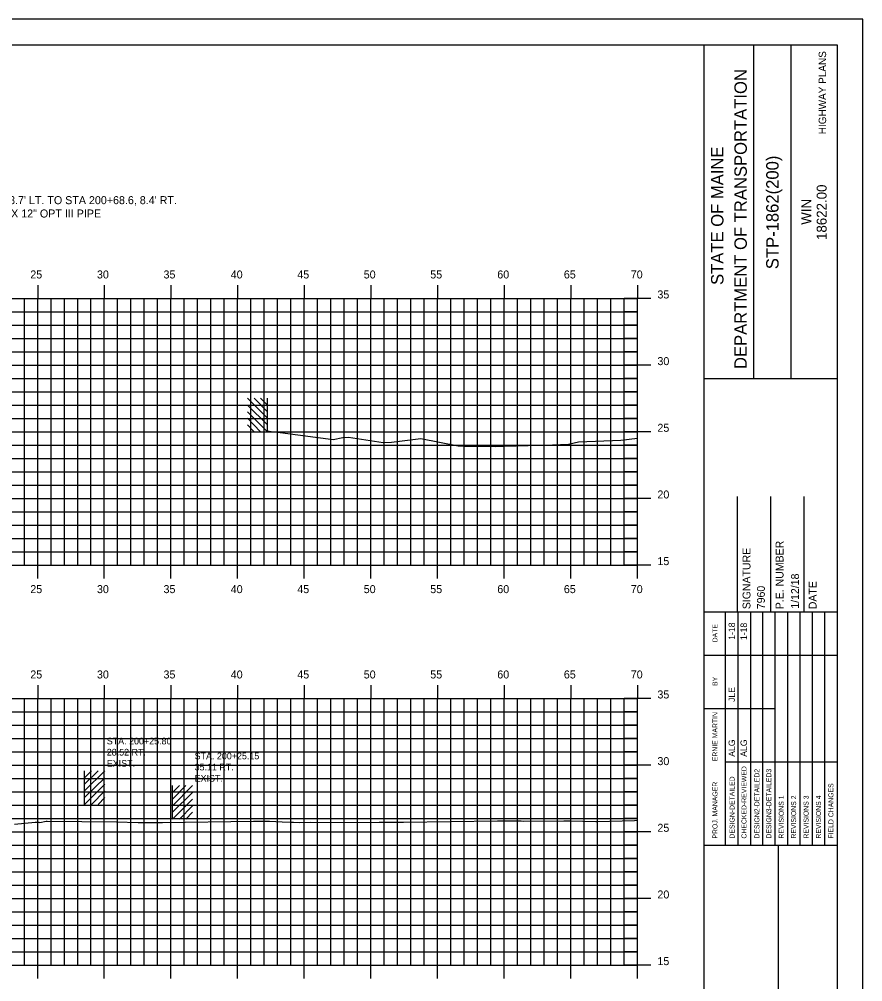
# Model space of a CAD drawing. Extents: x 1023237 to 1023407, y 394697 to 394807.
# Drawn here: x 1023343.3 to 1023406.6, y 394734.4 to 394806.5 of the extents above; entities that cross this region are included whole.
import ezdxf

# ---------------------------------------------------------------- set-up
doc = ezdxf.new("R2010")
doc.units = 0
for name, color, linetype in [('BORDER', 7, 'Continuous'), ('D_Drainage_Text', 7, 'Continuous'), ('D_Text_Monospaced', 7, 'Continuous'), ('H_V ANNOTATION', 7, 'Continuous'), ('HIGHWAY_TITLE', 7, 'Continuous'), ('MAJOR', 7, 'Continuous'), ('MINOR', 7, 'Continuous'), ('PLOT BOUNDARY', 7, 'Continuous'), ('S_Buildings_SillElevation', 7, 'Continuous'), ('S_Roadway_Centerline', 7, 'Continuous')]:
    doc.layers.add(name, color=color, linetype=linetype)

msp = doc.modelspace()

# ---------------------------------------------------------------- linework, layer by layer
at = {"layer": 'BORDER'}
for p, q in [((1023404.664, 394804.607), (1023244.664, 394804.607)), ((1023394.664, 394699.607), (1023394.664, 394804.61)), ((1023398.392, 394779.604), (1023398.392, 394804.604)), ((1023401.187, 394779.604), (1023401.187, 394804.604)), ((1023404.664, 394699.607), (1023404.664, 394804.607)), ((1023394.664, 394779.601), (1023404.664, 394779.601)), ((1023397.164, 394762.11), (1023397.164, 394770.757)), ((1023399.664, 394762.11), (1023399.664, 394770.757)), ((1023402.164, 394762.11), (1023402.164, 394770.757)), ((1023394.664, 394762.11), (1023404.664, 394762.11)), ((1023394.664, 394744.61), (1023404.664, 394744.61)), ((1023400.255, 394709.61), (1023400.255, 394744.61))]:
    msp.add_line(p, q, dxfattribs=at)
for points in [[(1023396.278, 394758.86), (1023396.278, 394762.11)], [(1023397.211, 394744.613), (1023397.211, 394762.11)], [(1023398.143, 394762.11), (1023398.143, 394744.613)], [(1023399.074, 394744.613), (1023399.074, 394762.11)], [(1023400.006, 394744.613), (1023400.006, 394762.11)], [(1023400.938, 394744.613), (1023400.938, 394762.11)], [(1023401.869, 394744.613), (1023401.869, 394762.11)], [(1023402.801, 394744.613), (1023402.801, 394762.11)], [(1023403.733, 394744.613), (1023403.733, 394762.11)], [(1023396.279, 394744.613), (1023396.279, 394761.404)], [(1023394.664, 394758.86), (1023404.664, 394758.86)], [(1023394.664, 394754.86), (1023396.279, 394754.86)], [(1023396.278, 394754.86), (1023400.005, 394754.86)], [(1023396.278, 394750.86), (1023404.664, 394750.86)]]:
    msp.add_lwpolyline(points, dxfattribs=at)
at = {"layer": 'MAJOR'}
for p, q in [((1023344.663, 394786.609), (1023344.663, 394785.607)), ((1023349.663, 394786.609), (1023349.663, 394785.607)), ((1023354.663, 394786.609), (1023354.663, 394785.607)), ((1023359.663, 394786.609), (1023359.663, 394785.607)), ((1023364.663, 394786.609), (1023364.663, 394785.607)), ((1023369.663, 394786.609), (1023369.663, 394785.607)), ((1023374.663, 394786.609), (1023374.663, 394785.607)), ((1023379.663, 394786.609), (1023379.663, 394785.607)), ((1023384.663, 394786.609), (1023384.663, 394785.607)), ((1023389.663, 394786.609), (1023389.663, 394785.607)), ((1023249.663, 394785.607), (1023389.663, 394785.607)), ((1023344.663, 394765.607), (1023344.663, 394785.607)), ((1023349.663, 394765.607), (1023349.663, 394785.607)), ((1023354.663, 394765.607), (1023354.663, 394785.607)), ((1023359.663, 394765.607), (1023359.663, 394785.607)), ((1023364.663, 394765.607), (1023364.663, 394785.607)), ((1023369.663, 394765.607), (1023369.663, 394785.607)), ((1023374.663, 394765.607), (1023374.663, 394785.607)), ((1023379.663, 394765.607), (1023379.663, 394785.607)), ((1023384.663, 394765.607), (1023384.663, 394785.607)), ((1023390.665, 394785.607), (1023388.661, 394785.607)), ((1023389.663, 394765.607), (1023389.663, 394785.607)), ((1023249.663, 394780.607), (1023389.663, 394780.607)), ((1023390.665, 394780.607), (1023388.661, 394780.607)), ((1023249.663, 394775.607), (1023389.663, 394775.607)), ((1023390.665, 394775.607), (1023388.661, 394775.607)), ((1023249.663, 394770.607), (1023389.663, 394770.607)), ((1023390.665, 394770.607), (1023388.661, 394770.607)), ((1023249.663, 394765.607), (1023389.663, 394765.607)), ((1023344.663, 394764.605), (1023344.663, 394765.607)), ((1023349.663, 394764.605), (1023349.663, 394765.607)), ((1023354.663, 394764.605), (1023354.663, 394765.607)), ((1023359.663, 394764.605), (1023359.663, 394765.607)), ((1023364.663, 394764.605), (1023364.663, 394765.607)), ((1023369.663, 394764.605), (1023369.663, 394765.607)), ((1023374.663, 394764.605), (1023374.663, 394765.607)), ((1023379.663, 394764.605), (1023379.663, 394765.607)), ((1023384.663, 394764.605), (1023384.663, 394765.607)), ((1023390.665, 394765.607), (1023388.661, 394765.607)), ((1023389.663, 394764.605), (1023389.663, 394765.607)), ((1023344.663, 394756.609), (1023344.663, 394755.607)), ((1023349.663, 394756.609), (1023349.663, 394755.607)), ((1023354.663, 394756.609), (1023354.663, 394755.607)), ((1023359.663, 394756.609), (1023359.663, 394755.607)), ((1023364.663, 394756.609), (1023364.663, 394755.607)), ((1023369.663, 394756.609), (1023369.663, 394755.607)), ((1023374.663, 394756.609), (1023374.663, 394755.607)), ((1023379.663, 394756.609), (1023379.663, 394755.607)), ((1023384.663, 394756.609), (1023384.663, 394755.607)), ((1023389.663, 394756.609), (1023389.663, 394755.607)), ((1023249.663, 394755.607), (1023389.663, 394755.607)), ((1023344.663, 394735.607), (1023344.663, 394755.607)), ((1023349.663, 394735.607), (1023349.663, 394755.607)), ((1023354.663, 394735.607), (1023354.663, 394755.607)), ((1023359.663, 394735.607), (1023359.663, 394755.607)), ((1023364.663, 394735.607), (1023364.663, 394755.607)), ((1023369.663, 394735.607), (1023369.663, 394755.607)), ((1023374.663, 394735.607), (1023374.663, 394755.607)), ((1023379.663, 394735.607), (1023379.663, 394755.607)), ((1023384.663, 394735.607), (1023384.663, 394755.607)), ((1023390.665, 394755.607), (1023388.661, 394755.607)), ((1023389.663, 394735.607), (1023389.663, 394755.607)), ((1023249.663, 394750.607), (1023389.663, 394750.607)), ((1023390.665, 394750.607), (1023388.661, 394750.607)), ((1023249.663, 394745.607), (1023389.663, 394745.607)), ((1023390.665, 394745.607), (1023388.661, 394745.607)), ((1023249.663, 394740.607), (1023389.663, 394740.607)), ((1023390.665, 394740.607), (1023388.661, 394740.607)), ((1023249.663, 394735.607), (1023389.663, 394735.607)), ((1023344.663, 394734.605), (1023344.663, 394735.607)), ((1023349.663, 394734.605), (1023349.663, 394735.607)), ((1023354.663, 394734.605), (1023354.663, 394735.607)), ((1023359.663, 394734.605), (1023359.663, 394735.607)), ((1023364.663, 394734.605), (1023364.663, 394735.607)), ((1023369.663, 394734.605), (1023369.663, 394735.607)), ((1023374.663, 394734.605), (1023374.663, 394735.607)), ((1023379.663, 394734.605), (1023379.663, 394735.607)), ((1023384.663, 394734.605), (1023384.663, 394735.607)), ((1023390.665, 394735.607), (1023388.661, 394735.607)), ((1023389.663, 394734.605), (1023389.663, 394735.607))]:
    msp.add_line(p, q, dxfattribs=at)
at = {"layer": 'MINOR'}
for p, q in [((1023343.663, 394765.607), (1023343.663, 394785.607)), ((1023345.663, 394765.607), (1023345.663, 394785.607)), ((1023346.663, 394765.607), (1023346.663, 394785.607)), ((1023347.663, 394765.607), (1023347.663, 394785.607)), ((1023348.663, 394765.607), (1023348.663, 394785.607)), ((1023350.663, 394765.607), (1023350.663, 394785.607)), ((1023351.663, 394765.607), (1023351.663, 394785.607)), ((1023352.663, 394765.607), (1023352.663, 394785.607)), ((1023353.663, 394765.607), (1023353.663, 394785.607)), ((1023355.663, 394765.607), (1023355.663, 394785.607)), ((1023356.663, 394765.607), (1023356.663, 394785.607)), ((1023357.663, 394765.607), (1023357.663, 394785.607)), ((1023358.663, 394765.607), (1023358.663, 394785.607)), ((1023360.663, 394765.607), (1023360.663, 394785.607)), ((1023361.663, 394765.607), (1023361.663, 394785.607)), ((1023362.663, 394765.607), (1023362.663, 394785.607)), ((1023363.663, 394765.607), (1023363.663, 394785.607)), ((1023365.663, 394765.607), (1023365.663, 394785.607)), ((1023366.663, 394765.607), (1023366.663, 394785.607)), ((1023367.663, 394765.607), (1023367.663, 394785.607)), ((1023368.663, 394765.607), (1023368.663, 394785.607)), ((1023370.663, 394765.607), (1023370.663, 394785.607)), ((1023371.663, 394765.607), (1023371.663, 394785.607)), ((1023372.663, 394765.607), (1023372.663, 394785.607)), ((1023373.663, 394765.607), (1023373.663, 394785.607)), ((1023375.663, 394765.607), (1023375.663, 394785.607)), ((1023376.663, 394765.607), (1023376.663, 394785.607)), ((1023377.663, 394765.607), (1023377.663, 394785.607)), ((1023378.663, 394765.607), (1023378.663, 394785.607)), ((1023380.663, 394765.607), (1023380.663, 394785.607)), ((1023381.663, 394765.607), (1023381.663, 394785.607)), ((1023382.663, 394765.607), (1023382.663, 394785.607)), ((1023383.663, 394765.607), (1023383.663, 394785.607)), ((1023385.663, 394765.607), (1023385.663, 394785.607)), ((1023386.663, 394765.607), (1023386.663, 394785.607)), ((1023387.663, 394765.607), (1023387.663, 394785.607)), ((1023388.663, 394765.607), (1023388.663, 394785.607)), ((1023249.663, 394784.607), (1023389.663, 394784.607)), ((1023389.663, 394784.607), (1023388.661, 394784.607)), ((1023249.663, 394783.607), (1023389.663, 394783.607)), ((1023389.663, 394783.607), (1023388.661, 394783.607)), ((1023249.663, 394782.607), (1023389.663, 394782.607)), ((1023389.663, 394782.607), (1023388.661, 394782.607)), ((1023249.663, 394781.607), (1023389.663, 394781.607)), ((1023389.663, 394781.607), (1023388.661, 394781.607)), ((1023249.663, 394779.607), (1023389.663, 394779.607)), ((1023389.663, 394779.607), (1023388.661, 394779.607)), ((1023249.663, 394778.607), (1023389.663, 394778.607)), ((1023389.663, 394778.607), (1023388.661, 394778.607)), ((1023249.663, 394777.607), (1023389.663, 394777.607)), ((1023389.663, 394777.607), (1023388.661, 394777.607)), ((1023249.663, 394776.607), (1023389.663, 394776.607)), ((1023389.663, 394776.607), (1023388.661, 394776.607)), ((1023249.663, 394774.607), (1023389.663, 394774.607)), ((1023389.663, 394774.607), (1023388.661, 394774.607)), ((1023249.663, 394773.607), (1023389.663, 394773.607)), ((1023389.663, 394773.607), (1023388.661, 394773.607)), ((1023249.663, 394772.607), (1023389.663, 394772.607)), ((1023389.663, 394772.607), (1023388.661, 394772.607)), ((1023249.663, 394771.607), (1023389.663, 394771.607)), ((1023389.663, 394771.607), (1023388.661, 394771.607)), ((1023249.663, 394769.607), (1023389.663, 394769.607)), ((1023389.663, 394769.607), (1023388.661, 394769.607)), ((1023249.663, 394768.607), (1023389.663, 394768.607)), ((1023389.663, 394768.607), (1023388.661, 394768.607)), ((1023249.663, 394767.607), (1023389.663, 394767.607)), ((1023389.663, 394767.607), (1023388.661, 394767.607)), ((1023249.663, 394766.607), (1023389.663, 394766.607)), ((1023389.663, 394766.607), (1023388.661, 394766.607)), ((1023343.663, 394735.607), (1023343.663, 394755.607)), ((1023345.663, 394735.607), (1023345.663, 394755.607)), ((1023346.663, 394735.607), (1023346.663, 394755.607)), ((1023347.663, 394735.607), (1023347.663, 394755.607)), ((1023348.663, 394735.607), (1023348.663, 394755.607)), ((1023350.663, 394735.607), (1023350.663, 394755.607)), ((1023351.663, 394735.607), (1023351.663, 394755.607)), ((1023352.663, 394735.607), (1023352.663, 394755.607)), ((1023353.663, 394735.607), (1023353.663, 394755.607)), ((1023355.663, 394735.607), (1023355.663, 394755.607)), ((1023356.663, 394735.607), (1023356.663, 394755.607)), ((1023357.663, 394735.607), (1023357.663, 394755.607)), ((1023358.663, 394735.607), (1023358.663, 394755.607)), ((1023360.663, 394735.607), (1023360.663, 394755.607)), ((1023361.663, 394735.607), (1023361.663, 394755.607)), ((1023362.663, 394735.607), (1023362.663, 394755.607)), ((1023363.663, 394735.607), (1023363.663, 394755.607)), ((1023365.663, 394735.607), (1023365.663, 394755.607)), ((1023366.663, 394735.607), (1023366.663, 394755.607)), ((1023367.663, 394735.607), (1023367.663, 394755.607)), ((1023368.663, 394735.607), (1023368.663, 394755.607)), ((1023370.663, 394735.607), (1023370.663, 394755.607)), ((1023371.663, 394735.607), (1023371.663, 394755.607)), ((1023372.663, 394735.607), (1023372.663, 394755.607)), ((1023373.663, 394735.607), (1023373.663, 394755.607)), ((1023375.663, 394735.607), (1023375.663, 394755.607)), ((1023376.663, 394735.607), (1023376.663, 394755.607)), ((1023377.663, 394735.607), (1023377.663, 394755.607)), ((1023378.663, 394735.607), (1023378.663, 394755.607)), ((1023380.663, 394735.607), (1023380.663, 394755.607)), ((1023381.663, 394735.607), (1023381.663, 394755.607)), ((1023382.663, 394735.607), (1023382.663, 394755.607)), ((1023383.663, 394735.607), (1023383.663, 394755.607)), ((1023385.663, 394735.607), (1023385.663, 394755.607)), ((1023386.663, 394735.607), (1023386.663, 394755.607)), ((1023387.663, 394735.607), (1023387.663, 394755.607)), ((1023388.663, 394735.607), (1023388.663, 394755.607)), ((1023249.663, 394754.607), (1023389.663, 394754.607)), ((1023389.663, 394754.607), (1023388.661, 394754.607)), ((1023249.663, 394753.607), (1023389.663, 394753.607)), ((1023389.663, 394753.607), (1023388.661, 394753.607)), ((1023249.663, 394752.607), (1023389.663, 394752.607)), ((1023389.663, 394752.607), (1023388.661, 394752.607)), ((1023249.663, 394751.607), (1023389.663, 394751.607)), ((1023389.663, 394751.607), (1023388.661, 394751.607)), ((1023249.663, 394749.607), (1023389.663, 394749.607)), ((1023389.663, 394749.607), (1023388.661, 394749.607)), ((1023249.663, 394748.607), (1023389.663, 394748.607)), ((1023389.663, 394748.607), (1023388.661, 394748.607)), ((1023249.663, 394747.607), (1023389.663, 394747.607)), ((1023389.663, 394747.607), (1023388.661, 394747.607)), ((1023249.663, 394746.607), (1023389.663, 394746.607)), ((1023389.663, 394746.607), (1023388.661, 394746.607)), ((1023249.663, 394744.607), (1023389.663, 394744.607)), ((1023389.663, 394744.607), (1023388.661, 394744.607)), ((1023249.663, 394743.607), (1023389.663, 394743.607)), ((1023389.663, 394743.607), (1023388.661, 394743.607)), ((1023249.663, 394742.607), (1023389.663, 394742.607)), ((1023389.663, 394742.607), (1023388.661, 394742.607)), ((1023249.663, 394741.607), (1023389.663, 394741.607)), ((1023389.663, 394741.607), (1023388.661, 394741.607)), ((1023249.663, 394739.607), (1023389.663, 394739.607)), ((1023389.663, 394739.607), (1023388.661, 394739.607)), ((1023249.663, 394738.607), (1023389.663, 394738.607)), ((1023389.663, 394738.607), (1023388.661, 394738.607)), ((1023249.663, 394737.607), (1023389.663, 394737.607)), ((1023389.663, 394737.607), (1023388.661, 394737.607)), ((1023249.663, 394736.607), (1023389.663, 394736.607)), ((1023389.663, 394736.607), (1023388.661, 394736.607))]:
    msp.add_line(p, q, dxfattribs=at)
at = {"layer": 'PLOT BOUNDARY'}
msp.add_lwpolyline([(1023236.57, 394696.548), (1023406.57, 394696.548), (1023406.57, 394806.548), (1023236.57, 394806.548)], close=True, dxfattribs=at)
at = {"layer": 'S_Buildings_SillElevation'}
for p, q in [((1023361.911, 394776.624), (1023360.402, 394778.133)), ((1023361.911, 394777.116), (1023360.894, 394778.133)), ((1023361.911, 394777.608), (1023361.386, 394778.133)), ((1023361.911, 394775.607), (1023361.911, 394778.133)), ((1023361.911, 394776.132), (1023360.402, 394777.608)), ((1023361.911, 394775.607), (1023360.402, 394777.116)), ((1023361.386, 394775.607), (1023360.402, 394776.624)), ((1023360.894, 394775.607), (1023360.402, 394776.132)), ((1023348.181, 394747.662), (1023348.181, 394750.189)), ((1023348.181, 394748.679), (1023349.69, 394750.189)), ((1023348.181, 394749.172), (1023349.198, 394750.189)), ((1023348.181, 394749.664), (1023348.706, 394750.189)), ((1023348.181, 394748.187), (1023349.69, 394749.664)), ((1023348.181, 394747.662), (1023349.69, 394749.172)), ((1023354.772, 394746.546), (1023354.772, 394749.072)), ((1023354.772, 394747.563), (1023356.281, 394749.072)), ((1023354.772, 394748.055), (1023355.789, 394749.072)), ((1023354.772, 394748.547), (1023355.297, 394749.072)), ((1023348.706, 394747.662), (1023349.69, 394748.679)), ((1023349.198, 394747.662), (1023349.69, 394748.187)), ((1023354.772, 394747.071), (1023356.281, 394748.547)), ((1023354.772, 394746.546), (1023356.281, 394748.055)), ((1023355.297, 394746.546), (1023356.281, 394747.563)), ((1023355.789, 394746.546), (1023356.281, 394747.071))]:
    msp.add_line(p, q, dxfattribs=at)
at = {"layer": 'S_Roadway_Centerline'}
for points in [[(1023361.911, 394775.667), (1023362.179, 394775.633), (1023362.864, 394775.545), (1023366.839, 394775.035), (1023367.554, 394775.169), (1023367.989, 394775.213), (1023370.581, 394774.814), (1023371.209, 394774.833), (1023373.403, 394775.116), (1023376.225, 394774.559), (1023376.702, 394774.536), (1023379.038, 394774.501), (1023379.654, 394774.533), (1023383.28, 394774.64), (1023384.493, 394774.677), (1023385.232, 394774.851), (1023388.407, 394774.984), (1023389.663, 394775.123)], [(1023342.935, 394746.177), (1023344.483, 394746.319), (1023344.758, 394746.33), (1023344.829, 394746.303), (1023345.31, 394746.396), (1023345.38, 394746.396), (1023350.573, 394746.363), (1023352.203, 394746.304), (1023352.356, 394746.305), (1023352.868, 394746.306), (1023353.006, 394746.301), (1023353.028, 394746.3), (1023353.042, 394746.3), (1023353.045, 394746.3), (1023353.049, 394746.306), (1023353.095, 394746.3), (1023353.101, 394746.3), (1023353.191, 394746.301), (1023353.202, 394746.301), (1023353.368, 394746.302), (1023353.948, 394746.306), (1023354.04, 394746.307), (1023360.864, 394746.395), (1023360.94, 394746.396), (1023361.474, 394746.401), (1023361.525, 394746.402), (1023361.657, 394746.405), (1023361.661, 394746.406), (1023361.668, 394746.405), (1023361.747, 394746.406), (1023362.06, 394746.395), (1023363.01, 394746.362), (1023363.668, 394746.339), (1023363.863, 394746.336), (1023364.329, 394746.314), (1023365.161, 394746.323), (1023369.642, 394746.31), (1023370.28, 394746.324), (1023372.112, 394746.33), (1023379.158, 394746.424), (1023380.946, 394746.435), (1023381.103, 394746.394), (1023384.132, 394746.435), (1023384.409, 394746.435), (1023384.588, 394746.433), (1023386.533, 394746.38), (1023386.648, 394746.377), (1023389.438, 394746.445), (1023389.663, 394746.47)]]:
    msp.add_lwpolyline(points, dxfattribs=at)

# ---------------------------------------------------------------- texts
at = {"layer": 'BORDER'}
for s, height, p in [('DEPARTMENT OF TRANSPORTATION', 0.93176, (1023397.87, 394780.313)), ('STATE OF MAINE', 0.93176, (1023396.119, 394786.619)), ('STP-1862(200)', 0.93176, (1023400.256, 394787.801)), ('18622.00', 0.7453, (1023403.859, 394789.993)), ('WIN', 0.7453, (1023402.7, 394791.137)), ('SIGNATURE', 0.5906, (1023398.144, 394762.302)), ('P.E. NUMBER', 0.59055, (1023400.624, 394762.302)), ('1/12/18', 0.5906, (1023401.785, 394762.337)), ('7960', 0.5906, (1023399.226, 394762.302)), ('DATE', 0.5906, (1023403.105, 394762.302)), ('DATE', 0.3714, (1023395.668, 394759.815)), ('1-18', 0.4845, (1023396.987, 394760.007)), ('1-18', 0.4845, (1023397.881, 394759.985)), ('BY', 0.3714, (1023395.668, 394756.545)), ('JLE', 0.4845, (1023396.987, 394755.345)), ('ERNIE MARTIN', 0.37275, (1023395.668, 394750.901)), ('ALG', 0.4845, (1023396.987, 394751.233)), ('ALG', 0.4845, (1023397.881, 394751.233)), ('CHECKED-REVIEWED', 0.37275, (1023397.845, 394745.098)), ('DESIGN-DETAILED', 0.37275, (1023396.95, 394745.098)), ('DESIGN2-DETAILED2', 0.37275, (1023398.814, 394745.098)), ('DESIGN3-DETAILED3', 0.37275, (1023399.708, 394745.098)), ('PROJ. MANAGER', 0.37275, (1023395.668, 394745.098)), ('FIELD CHANGES', 0.37275, (1023404.366, 394745.098)), ('REVISIONS 1', 0.37275, (1023400.64, 394745.098)), ('REVISIONS 2', 0.37275, (1023401.571, 394745.098)), ('REVISIONS 3', 0.37275, (1023402.503, 394745.098)), ('REVISIONS 4', 0.37275, (1023403.435, 394745.098))]:
    msp.add_text(s, height=height, rotation=90, dxfattribs=at).set_placement(p)
at = {"layer": 'D_Drainage_Text'}
for s, p in [("STA 200+37.9, 8.7' LT. TO STA 200+68.6, 8.4' RT.", (1023336.918, 394792.679)), ('INSTALL 36 LF X 12" OPT III PIPE', (1023336.918, 394791.679))]:
    msp.add_text(s, height=0.6, dxfattribs=at).set_placement(p)
at = {"layer": 'D_Text_Monospaced'}
for s, height, p in [('STA. 200+25.80', 0.49998, (1023349.848, 394752.161)), ('28.52 RT.', 0.5, (1023349.848, 394751.327)), ('EXIST. ', 0.5, (1023349.848, 394750.487)), ('STA. 200+25.15', 0.49998, (1023356.439, 394751.044)), ('35.11 RT.', 0.5, (1023356.439, 394750.21)), ('EXIST. ', 0.5, (1023356.439, 394749.37))]:
    msp.add_text(s, height=height, dxfattribs=at).set_placement(p)
at = {"layer": 'H_V ANNOTATION'}
for s, p in [('25', (1023344.109, 394787.107)), ('30', (1023349.112, 394787.107)), ('35', (1023354.104, 394787.107)), ('40', (1023359.15, 394787.107)), ('45', (1023364.142, 394787.107)), ('50', (1023369.128, 394787.107)), ('55', (1023374.12, 394787.107)), ('60', (1023379.15, 394787.107)), ('65', (1023384.142, 394787.107)), ('70', (1023389.165, 394787.107)), ('35', (1023391.163, 394785.607)), ('30', (1023391.163, 394780.607)), ('25', (1023391.163, 394775.607)), ('20', (1023391.163, 394770.607)), ('15', (1023391.163, 394765.607)), ('25', (1023344.109, 394763.507)), ('30', (1023349.112, 394763.507)), ('35', (1023354.104, 394763.507)), ('40', (1023359.15, 394763.507)), ('45', (1023364.142, 394763.507)), ('50', (1023369.128, 394763.507)), ('55', (1023374.12, 394763.507)), ('60', (1023379.15, 394763.507)), ('65', (1023384.142, 394763.507)), ('70', (1023389.165, 394763.507)), ('25', (1023344.109, 394757.107)), ('30', (1023349.112, 394757.107)), ('35', (1023354.104, 394757.107)), ('40', (1023359.15, 394757.107)), ('45', (1023364.142, 394757.107)), ('50', (1023369.128, 394757.107)), ('55', (1023374.12, 394757.107)), ('60', (1023379.15, 394757.107)), ('65', (1023384.142, 394757.107)), ('70', (1023389.165, 394757.107)), ('35', (1023391.163, 394755.607)), ('30', (1023391.163, 394750.607)), ('25', (1023391.163, 394745.607)), ('20', (1023391.163, 394740.607)), ('15', (1023391.163, 394735.607))]:
    msp.add_text(s, height=0.6, dxfattribs=at).set_placement(p)
at = {"layer": 'HIGHWAY_TITLE'}
msp.add_text('HIGHWAY PLANS', height=0.55901, rotation=90, dxfattribs=at).set_placement((1023403.822, 394797.922))

doc.saveas('drawing.dxf')
